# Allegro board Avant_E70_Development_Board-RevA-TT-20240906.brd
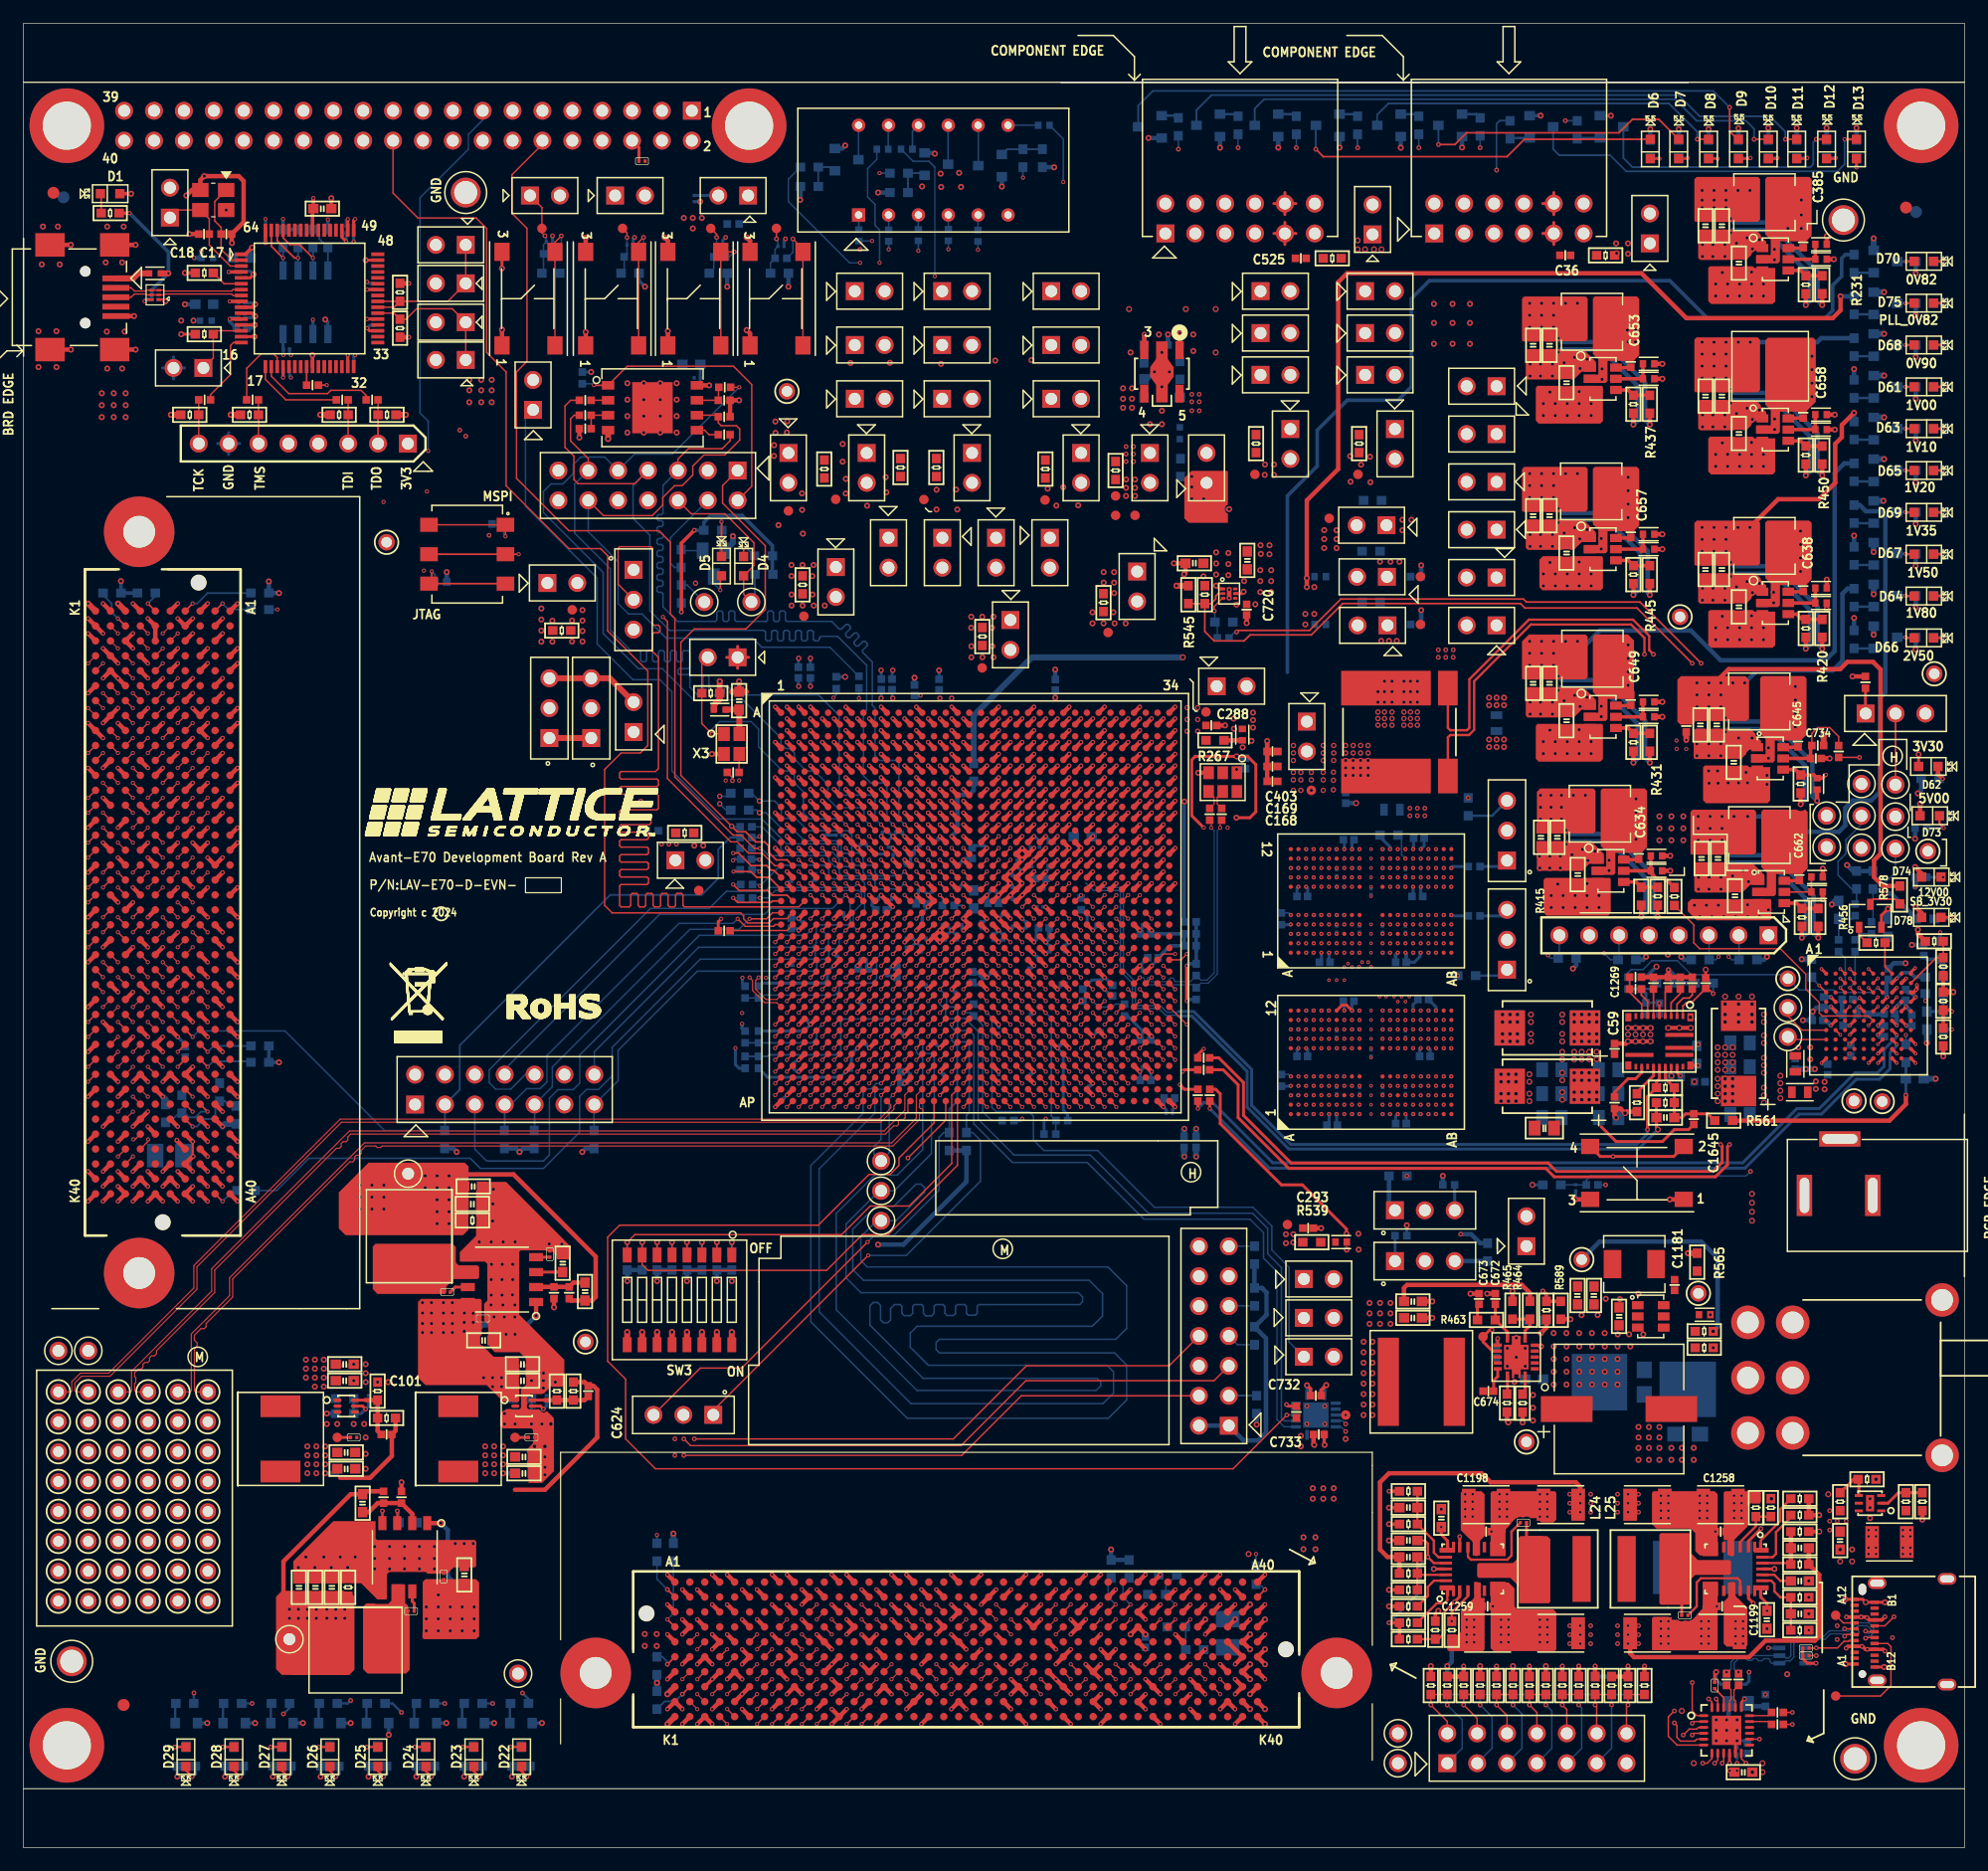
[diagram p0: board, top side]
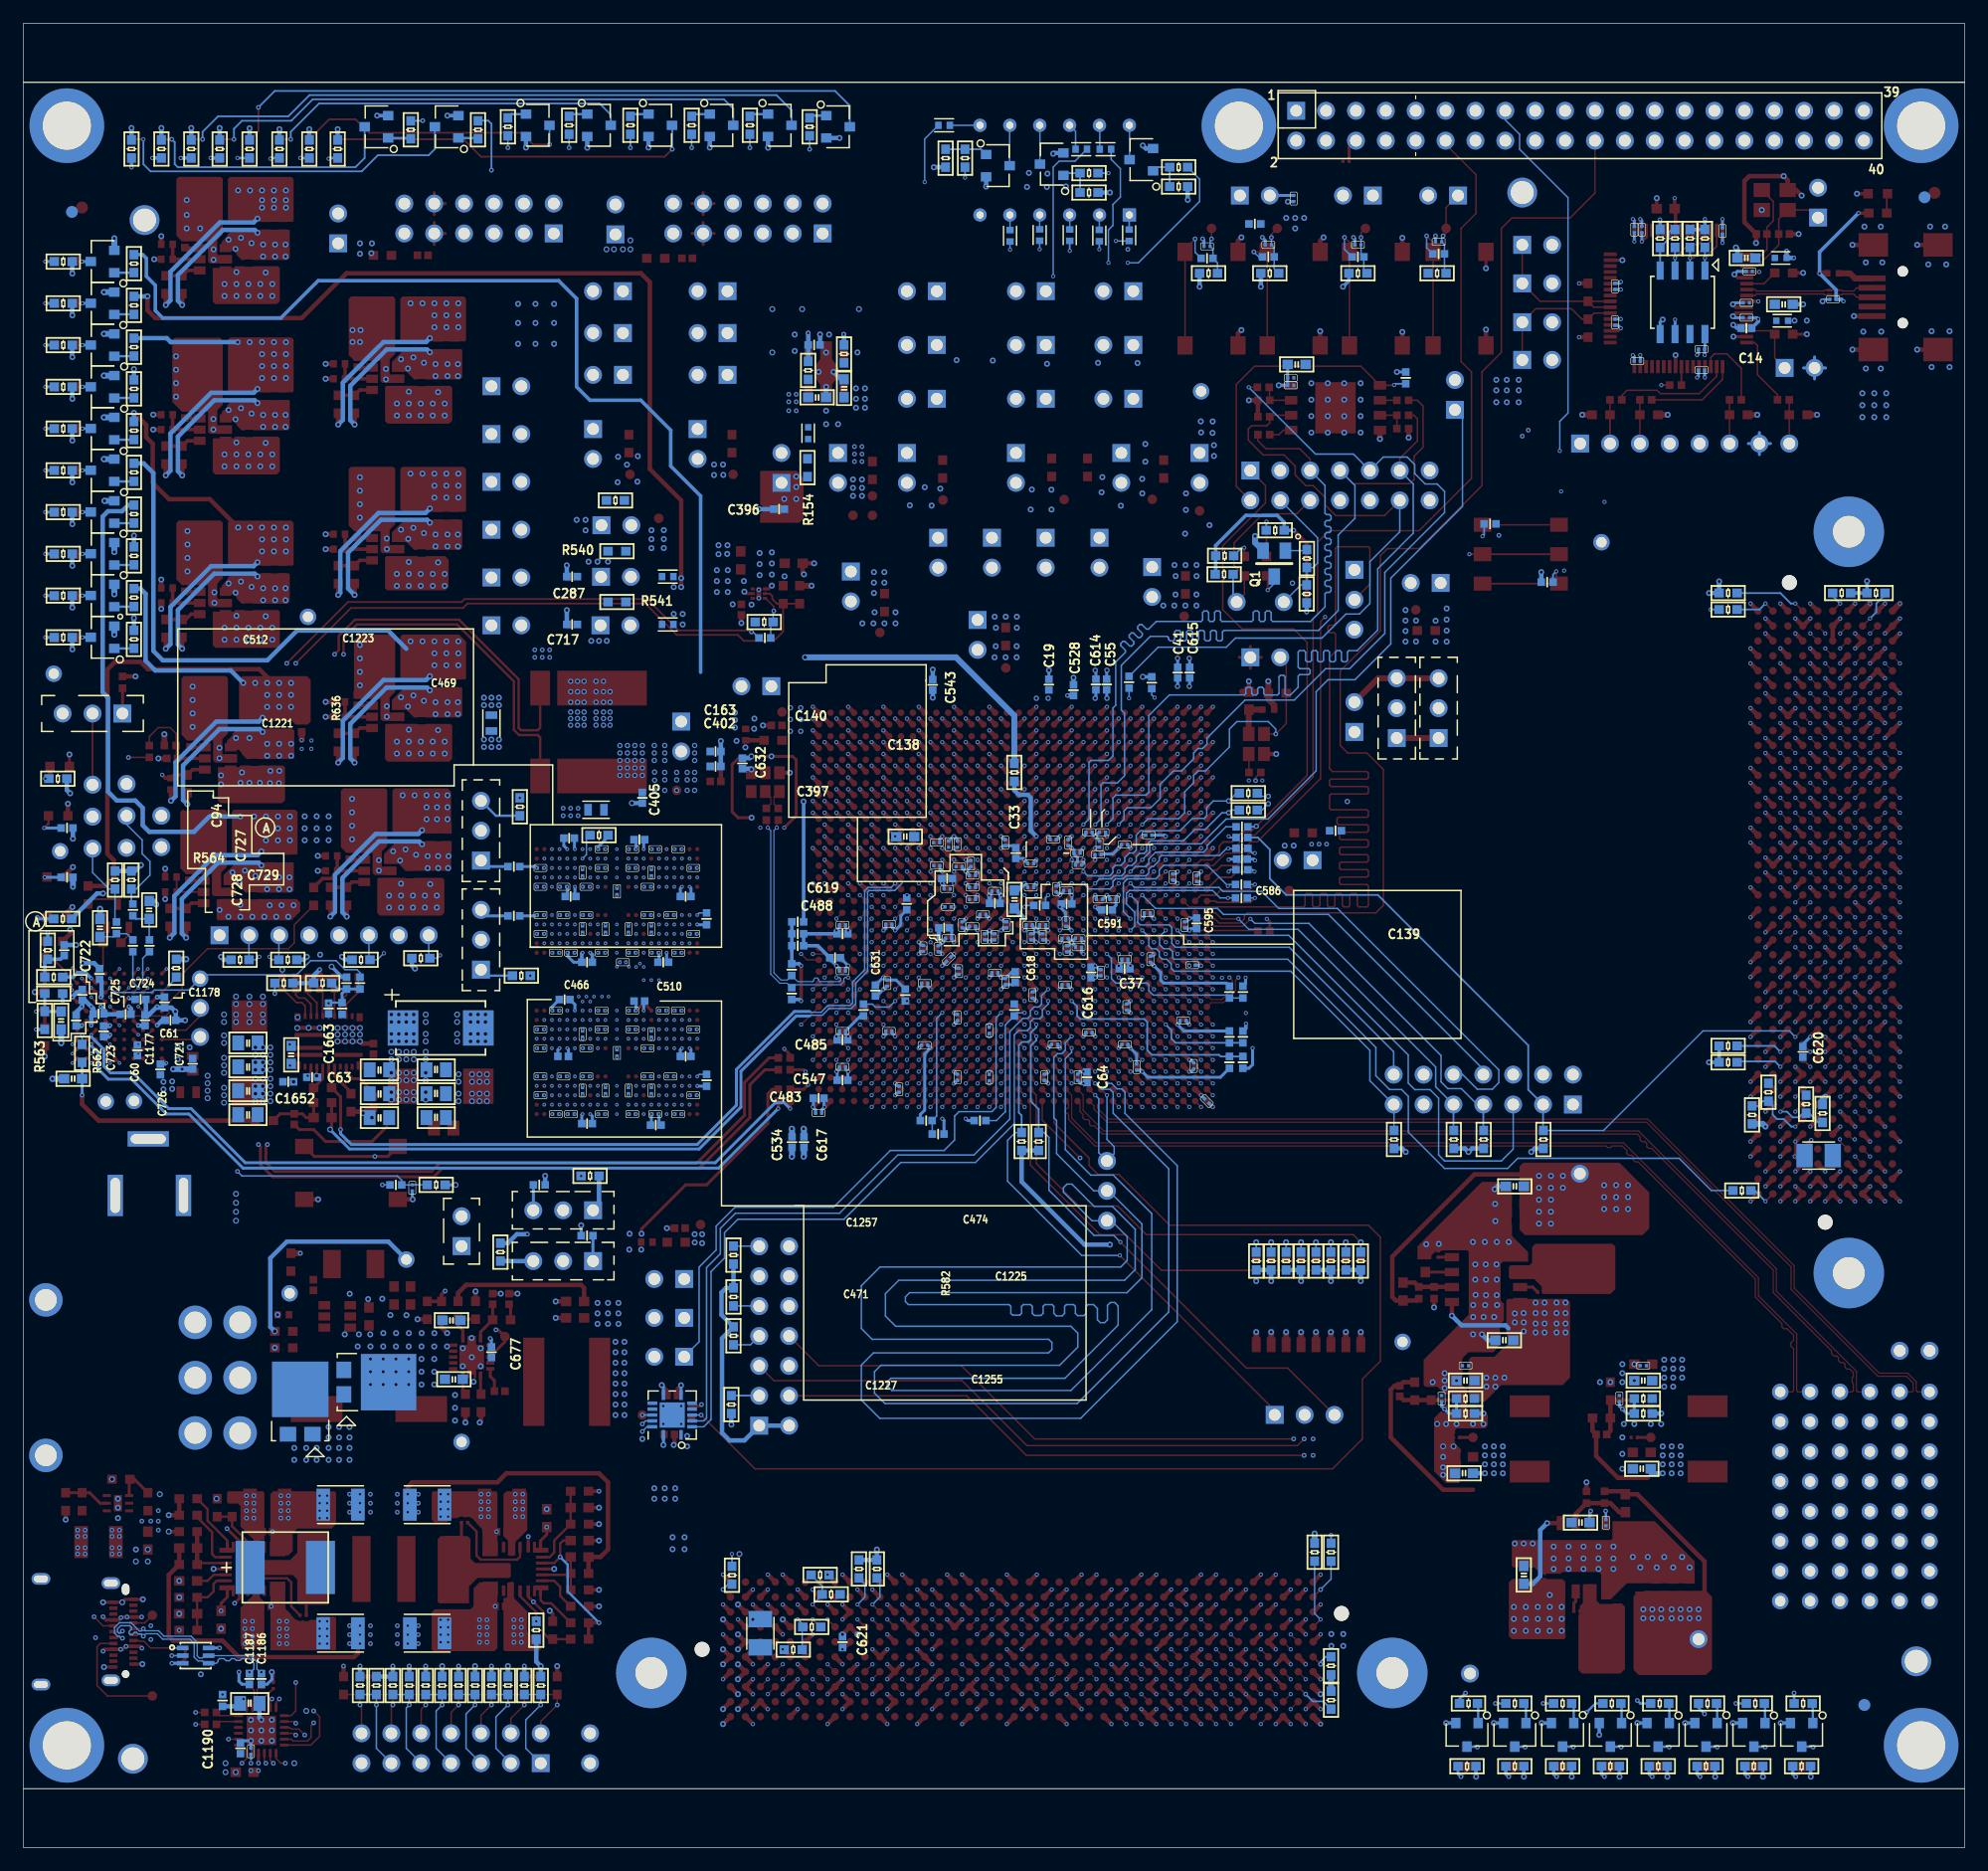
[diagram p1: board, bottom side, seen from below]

Outline 165 x 155 mm; copper layers: TOP, L02-GND, L03-SIG1, L04-GND, L05-SIG2, L06-GND, L07_POW1, L08-POW2, L09-GND, L10-SIG3, L11-GND, L12-SIG4, L13-GND, BOTTOM. Coordinates in mm from the lower left corner of the outline.
Outline path: 0,150 0,155 165,155 165,150 ; 0,150 0,5 ; 0,150 165,150 ; 0,150 165,150 ; 0,150 165,150 ; 0,5 0,0 165,0 165,5 ; 0,5 165,5 ; 0,5 165,5 ; 165,150 165,5

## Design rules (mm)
net group DIFFPAIR4: nets DM DP
net group DP1: nets EPS1_AN13_P EPS1_AP13_N
net group DP2: nets EPS2_AJ16 EPS2_AK16
net group DP3: nets EPS3_AL13_P EPS3_AM13_N
net group DP4: nets EPS4_AG15_P EPS4_AH15_N
net group DP5: nets EPS5_AK12_N EPS5_AK13_P
net group DP6: nets EPS6_AF15_P EPS6_AF16_N
net group DP7: nets EPS7_AN12_N EPS7_AP12_P
net group DP8: nets EPS8_AG14_N EPS8_AH14_P
net group DP9: nets EPS9_AP10_P EPS9_AP11_N
net group DP10: nets EPS10_AK14_P EPS10_AK15_N
net group DP13: nets N21269868 N21466678
net group F_DDR_100MHZ: nets F_DDR_100MHZ_N F_DDR_100MHZ_P
net group LPDDR4_LDM_A: nets LPDDR4_LDQS_A_N LPDDR4_LDQS_A_P
net group LPDDR4_LDM_C: nets LPDDR4_LDQS_C_N LPDDR4_LDQS_C_P
net group LPDDR4_UDM_A: nets LPDDR4_UDQS_A_N LPDDR4_UDQS_A_P
net group LPDDR4_UDM_C: nets LPDDR4_UDQS_C_N LPDDR4_UDQS_C_P
net group LPDDR4_UDM_D: nets LPDDR4_UDQS_D_N LPDDR4_UDQS_D_P
net group PWR: nets VBUS_5V00 VCCBAT_1V50
net group USB_DM: nets N22506509 USB_DM
net group USB_DP: nets N22506512 USB_DP
net group J48_FMC: nets FMC1_CLK0_M2C_N FMC1_CLK0_M2C_P FMC1_CLK1_M2C_N FMC1_CLK1_M2C_P FMC1_CLK3_M2C_N FMC1_CLK3_M2C_P FMC1_HA00_CLK_N FMC1_HA00_CLK_P FMC1_HA01_CLK_N FMC1_HA01_CLK_P FMC1_HA02_N FMC1_HA02_P FMC1_HA04_N FMC1_HA04_P FMC1_HA05_N FMC1_HA05_P FMC1_HA06_N FMC1_HA06_P FMC1_HA10_N FMC1_HA10_P FMC1_HA11_N FMC1_HA11_P FMC1_HA13_N FMC1_HA13_P FMC1_HA14_N FMC1_HA14_P FMC1_HA15_N FMC1_HA15_P FMC1_HA16_N FMC1_HA16_P FMC1_HA18_N FMC1_HA18_P FMC1_HA19_N FMC1_HA19_P FMC1_HA20_N FMC1_HA20_P FMC1_HA21_N FMC1_HA21_P FMC1_HA22_N FMC1_HA22_P FMC1_HA23_N FMC1_HA23_P FMC1_LA00_CLK_N FMC1_LA00_CLK_P FMC1_LA02_N FMC1_LA02_P FMC1_LA03_N FMC1_LA03_P FMC1_LA04_N FMC1_LA04_P FMC1_LA08_N FMC1_LA08_P FMC1_LA09_N FMC1_LA09_P FMC1_LA11_N FMC1_LA11_P FMC1_LA12_N FMC1_LA12_P FMC1_LA13_N FMC1_LA13_P FMC1_LA14_N FMC1_LA14_P FMC1_LA15_N FMC1_LA15_P FMC1_LA16_N FMC1_LA16_P FMC1_LA17_CLK_N FMC1_LA17_CLK_P FMC1_LA18_CLK_N FMC1_LA18_CLK_P FMC1_LA21_N FMC1_LA21_P FMC1_LA22_N FMC1_LA22_P FMC1_LA23_N FMC1_LA23_P FMC1_LA24_N FMC1_LA24_P FMC1_LA25_N FMC1_LA25_P FMC1_LA26_N FMC1_LA26_P FMC1_LA27_N FMC1_LA27_P FMC1_LA28_N FMC1_LA28_P FMC1_LA30_N FMC1_LA30_P FMC1_LA31_N FMC1_LA31_P FMC1_LA32_N FMC1_LA32_P FMC1_LA33_N FMC1_LA33_P
net group J54_FMC: nets FMC2_CLK0_M2C_N FMC2_CLK0_M2C_P FMC2_HA00_CLK_N FMC2_HA00_CLK_P FMC2_HA01_CLK_N FMC2_HA01_CLK_P FMC2_HA02_N FMC2_HA02_P FMC2_HA05_N FMC2_HA05_P FMC2_HA06_N FMC2_HA06_P FMC2_HA07_N FMC2_HA07_P FMC2_HA08_N FMC2_HA08_P FMC2_HA09_N FMC2_HA09_P FMC2_HA10_N FMC2_HA10_P FMC2_HA11_N FMC2_HA11_P FMC2_LA01_CLK_N FMC2_LA01_CLK_P FMC2_LA02_N FMC2_LA02_P FMC2_LA03_N FMC2_LA03_P FMC2_LA04_N FMC2_LA04_P FMC2_LA05_N FMC2_LA05_P FMC2_LA06_N FMC2_LA06_P FMC2_LA07_N FMC2_LA07_P FMC2_LA08_N FMC2_LA08_P FMC2_LA10_N FMC2_LA10_P FMC2_LA11_N FMC2_LA11_P FMC2_LA12_N FMC2_LA12_P FMC2_LA14_N FMC2_LA14_P FMC2_LA15_N FMC2_LA15_P FMC2_LA16_N FMC2_LA16_P FMC2_LA17_CLK_N FMC2_LA17_CLK_P FMC2_LA18_CLK_N FMC2_LA18_CLK_P FMC2_LA19_N FMC2_LA19_P FMC2_LA20_N FMC2_LA20_P FMC2_LA21_N FMC2_LA21_P FMC2_LA22_N FMC2_LA22_P FMC2_LA24_N FMC2_LA24_P FMC2_LA27_N FMC2_LA27_P FMC2_LA29_N FMC2_LA29_P FMC2_LA30_N FMC2_LA30_P FMC2_LA31_N FMC2_LA31_P FMC2_LA32_N FMC2_LA32_P FMC2_LA33_N FMC2_LA33_P
net group LED: nets LED_0 LED_1 LED_2 LED_3 LED_4 LED_5 LED_6 LED_7 LED_8 LED_9 LED_10 LED_11 LED_12 LED_13 LED_14 LED_15
net group LPDDR4_UDM_B: nets LPDDR4_DQ8_B LPDDR4_DQ9_B LPDDR4_DQ10_B LPDDR4_DQ11_B LPDDR4_DQ12_B LPDDR4_DQ13_B LPDDR4_DQ14_B LPDDR4_DQ15_B LPDDR4_UDM_B LPDDR4_UDQS_B_N LPDDR4_UDQS_B_P
net group POWER: nets FMC1_VREFA FMC2_VREFA N23029118
net group USB_VBUS: nets N22506572

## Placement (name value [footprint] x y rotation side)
AP14  TestPoint_SMT  [TPC32]  112.4 36.75 0 top
ASC_CLK  VTTVREF  [TP_50]  149.99 71.34 0 top
C1  0.1uF  [C0201]  27.81 126.31 0 bottom
C2  0.1uF  [C0201]  29.72 132.66 90 bottom
C3  0.1uF  [C0201]  22.35 125.55 0 bottom
C4  0.1uF  [C0201]  27.43 137.49 270 bottom
C5  4.7uF  [C0603]  25.4 139.27 0 top
C6  4.7uF  [C0603]  15.37 131.14 180 bottom
C7  0.1uF  [C0201]  18.54 131.27 0 bottom
C8  0.1uF  [C0201]  11.18 131.56 0 bottom
C9  4.7uF  [C0603]  18.54 135.08 0 bottom
C10  0.1uF  [C0201]  18.29 133.93 0 bottom
C11  0.1uF  [C0201]  29.72 129.62 270 bottom
C12  0.1uF  [C0201]  28.07 137.49 270 bottom
C13  0.1uF  [C0201]  20.57 137.36 90 bottom
C14  10uF  [C0402]  18.54 129.11 0 bottom
C15  0.1uF  [C0201]  18.54 130 0 bottom
C16  0.1uF  [C0201]  22.35 127.33 0 bottom
C17  18pF  [C0402]  17.24 137.11 180 top
C18  18pF  [C0402]  15.34 137.11 0 top
C19  10uF  [C0402]  77.83 98.82 90 bottom
C20  0.1uF  [C0201]  73.53 85.26 90 bottom
C21  0.1uF  [C0201]  51.56 136.19 0 bottom
C22  0.1uF  [C0201]  44.7 136.44 0 bottom
C23  0.1uF  [C0201]  57.28 124.25 0 bottom
C24  0.1uF  [C0201]  57.28 124.89 180 bottom
C25  1uF  [C0603]  56.77 126.03 180 bottom
C26  0.1uF  [C0201]  59.18 136.19 0 bottom
C27  0.1uF  [C0201]  64.39 136.06 0 bottom
C29  50pF  [C0603]  158.5 78.15 270 bottom
C30  50pF  [C0603]  154.31 79.68 270 bottom
C31  0.1uF  [C0201]  77.47 85.64 0 bottom
C32  0.1uF  [C0201]  81.53 85.39 90 bottom
C33  10uF  [C0402]  80.65 84.5 270 bottom
C34  0.1uF  [C0201]  131.95 56.05 270 bottom
C36  10uF  [C0402]  131.06 135.3 180 top
C37  10uF  [C0402]  71.4 74.67 180 bottom
C38  0.1uF  [C0201]  73.41 74.34 90 bottom
C39  0.1uF  [C0201]  71.37 75.48 180 bottom
C40  0.1uF  [C0201]  65.66 74.98 180 bottom
C41  10uF  [C0402]  66.89 99.84 90 bottom
C42  0.1uF  [C0201]  66.42 70.28 180 bottom
C43  0.1uF  [C0201]  64.41 63.43 225 bottom
C44  0.1uF  [C0201]  71.25 71.42 270 bottom
C45  10uF  [C0603]  39.12 43.1 0 top
C46  0.1uF  [C0201]  39.05 44.96 0 top
C47  10uF  [C0603]  39.12 43.1 0 bottom
C48  0.1uF  [C0201]  36.01 47.2 180 top
C49  22uF  [C0603]  38.23 56.18 0 bottom
C50  22uF  [C0603]  38.23 56.18 0 top
C51  22uF  [C0603]  38.16 54.68 0 top
C52  0.1nF  [C0603]  47.73 47.24 90 top
C53  1uF  [C0603]  45.83 49.66 90 top
C54  3.3nF  [C0201]  44.74 50.43 90 top
C55  10uF  [C0402]  72.92 98.84 90 bottom
C56  0.1uF  [C0201]  76.45 73.33 180 bottom
C57  0.1uF  [C0201]  70.38 66.32 90 bottom
C58  0.1uF  [C0201]  74.42 69.26 180 bottom
C59  1uF  [C0402]  135.25 67.86 90 top
C60  0.1uF  [C0402]  155.32 67.74 270 bottom
C61  0.1uF  [C0402]  152.51 70.3 180 bottom
C62  33nF  [C0603]  139.57 62.02 180 top
C63  1uF  [C0402]  140.46 65.45 180 bottom
C64  10uF  [C0402]  74.6 65.45 270 bottom
C65  0.1uF  [C0201]  79.25 72.44 270 bottom
C66  0.1uF  [C0201]  75.39 65.45 270 bottom
C69  1uF  [C0603]  60.83 97.46 90 top
C94  10nF  [C0402]  161.54 76.25 90 bottom
C97  10uF  [C0603]  27.3 39.67 0 top
C98  10uF  [C0603]  27.3 39.67 0 bottom
C99  0.1uF  [C0201]  27.3 40.94 0 bottom
C100  0.1uF  [C0201]  28.07 34.84 0 top
C101  18pF-DNI  [C0402]  30.86 35.1 180 top
C103  22uF  [C0603]  27.43 33.57 0 top
C104  22uF  [C0603]  27.43 32.18 0 bottom
C113  560 uF/25V  [RAD_CAN_A768MS]  135.64 37.26 180 top
C138  10uF  [C0402]  82.43 80.23 0 bottom
C139  10uF  [C0402]  76.33 80.18 180 bottom
C140  10uF  [C0402]  86.49 82.34 180 bottom
C142  0.1uF  [C0201]  87.36 83.44 180 bottom
C143  0.1uF  [C0201]  76.33 81.33 0 bottom
C144  0.1uF  [C0201]  85.6 85.26 90 bottom
C145  0.1uF  [C0201]  84.33 80.56 180 bottom
C146  0.1uF  [C0201]  87.38 85.39 180 bottom
C147  0.1uF  [C0201]  76.45 77.26 180 bottom
C148  0.1uF  [C0201]  82.42 81.29 180 bottom
C149  0.1uF  [C0201]  86.49 81.45 0 bottom
C150  0.1uF  [C0201]  85.47 83.36 180 bottom
C151  0.1uF  [C0201]  84.33 81.58 0 bottom
C152  0.1uF  [C0201]  79.5 78.41 180 bottom
C163  10uF  [C0402]  106.17 93.14 0 bottom
C164  0.1uF  [C0201]  82.42 77.39 90 bottom
C165  0.1uF  [C0201]  84.33 78.28 0 bottom
C166  0.1uF  [C0201]  75.31 76.5 0 bottom
C167  0.1uF  [C0201]  86.36 75.48 315 bottom
C168  10uF  [C0402]  106.17 90.6 0 top
C169  10uF  [C0402]  106.17 91.87 0 top
C171  0.1uF  [C0201]  84.46 83.61 270 bottom
C172  0.1uF  [C0201]  83.44 79.29 0 bottom
C173  0.1uF  [C0201]  76.4 78.53 90 bottom
C174  0.1uF  [C0201]  86.36 85.26 90 bottom
C175  0.1uF  [C0201]  85.22 78.41 270 bottom
C176  0.1uF  [C0201]  78.36 78.41 0 bottom
C177  0.1uF  [C0201]  83.31 77.39 90 bottom
C178  0.1uF  [C0201]  84.33 82.6 0 bottom
C207  10uF  [C0603]  95.25 124 90 bottom
C208  10uF  [C0603]  97.54 123.24 180 bottom
C287  10nF  [C0402]  118.36 108 0 bottom
C288  10nF  [C0402]  100.97 95.35 0 top
C289  0.1uF  [C0201]  76.33 76.37 90 bottom
C290  0.1uF  [C0201]  87.25 76.37 90 bottom
C291  0.1uF  [C0201]  75.31 83.49 0 bottom
C292  0.1uF  [C0201]  79.38 77.39 90 bottom
C293  10nF  [C0402]  109.2 52.63 0 top
C385  0.1uF  [C0402]  151.28 136.4 90 top
C386  22uF  [C0603]  144.39 137.81 270 top
C387  22uF  [C0603]  142.99 137.81 270 top
C388  10uF  [C0603]  145.82 134.64 90 top
C396  10uF  [C0402]  100.77 113.73 0 bottom
C397  10uF  [C0402]  86.74 78.15 0 bottom
C398  0.1uF  [C0201]  86.36 77.26 0 bottom
C399  0.1uF  [C0201]  81.41 78.41 90 bottom
C400  0.1uF  [C0201]  73.66 84.37 180 bottom
C401  0.1uF  [C0201]  75.31 77.26 0 bottom
C402  10uF  [C0402]  106.17 91.87 0 bottom
C403  10uF  [C0402]  106.17 93.14 0 top
C404  0.1uF  [C0201]  78.36 77.39 90 bottom
C405  10uF  [C0402]  112.4 89.2 90 bottom
C465  0.1uF  [C0201]  91.44 78.46 0 bottom
C466  10uF  [C0402]  117.09 75.23 0 bottom
C467  0.1uF  [C0201]  110 79.24 0 bottom
C468  0.1uF  [C0201]  88.5 76.41 90 bottom
C469  10uF  [C0402]  108.71 80.82 0 bottom
C470  0.1uF  [C0201]  108.05 83.24 180 bottom
C471  10uF  [C0402]  119.13 67.23 180 bottom
C472  0.1uF  [C0201]  113.25 84.84 180 bottom
C473  0.1uF  [C0201]  88.39 73.45 0 bottom
C474  10uF  [C0402]  112.65 71.93 0 bottom
C475  0.1uF  [C0201]  113.25 62.32 180 bottom
C476  0.1uF  [C0201]  85.47 74.47 270 bottom
C477  0.1uF  [C0201]  119.75 62.32 0 bottom
C478  0.1uF  [C0201]  91.57 73.45 270 bottom
C479  0.1uF  [C0201]  121.05 65.52 0 bottom
C480  0.1uF  [C0201]  95.38 74.47 0 bottom
C481  0.1uF  [C0201]  121.05 63.92 0 bottom
C482  0.1uF  [C0201]  119.1 65.52 180 bottom
C483  10uF  [C0402]  97.41 63.67 0 bottom
C484  0.1uF  [C0201]  109.35 71.12 180 bottom
C485  10uF  [C0402]  95.38 68.63 0 bottom
C486  0.1uF  [C0201]  121.05 67.92 0 bottom
C487  0.1uF  [C0201]  117.48 78.04 270 bottom
C488  10uF  [C0402]  96.01 75.61 0 bottom
C489  0.1uF  [C0201]  111.63 82.84 90 bottom
C490  0.1uF  [C0201]  121.05 69.52 0 bottom
C491  0.1uF  [C0201]  117.48 82.84 90 bottom
C492  0.1uF  [C0201]  115.85 69.52 0 bottom
C493  0.1uF  [C0201]  111.3 84.84 0 bottom
C494  0.1uF  [C0201]  111.63 78.04 270 bottom
C495  0.1uF  [C0201]  117.15 65.52 0 bottom
C496  0.1uF  [C0201]  111.3 76.04 0 bottom
C497  0.1uF  [C0201]  118.45 76.04 0 bottom
C498  0.1uF  [C0201]  111.95 67.92 180 bottom
C499  0.1uF  [C0201]  113.25 71.12 180 bottom
C500  0.1uF  [C0201]  109.35 84.84 180 bottom
C501  0.1uF  [C0201]  111.95 79.24 180 bottom
C502  0.1uF  [C0201]  108.06 77.64 180 bottom
C503  0.1uF  [C0201]  113.25 76.04 180 bottom
C504  0.1uF  [C0201]  109.35 76.04 180 bottom
C505  0.1uF  [C0201]  113.58 78.04 90 bottom
C506  0.1uF  [C0201]  111.95 81.64 180 bottom
C507  0.1uF  [C0201]  86.41 79.93 0 bottom
C508  0.1uF  [C0201]  113.25 83.24 180 bottom
C509  0.1uF  [C0201]  95.38 78.41 0 bottom
C510  10uF  [C0402]  110.62 75.23 180 bottom
C511  0.1uF  [C0201]  115.53 64.32 90 bottom
C512  10uF  [C0402]  118.62 85.77 0 bottom
C525  10uF  [C0402]  108.59 135.05 180 top
C526  0.1uF  [C0201]  79.38 83.61 0 bottom
C527  0.1uF  [C0201]  77.22 81.45 270 bottom
C528  10uF  [C0402]  75.74 98.34 90 bottom
C529  0.1uF  [C0201]  76.2 85.39 270 bottom
C530  0.1uF  [C0201]  79.38 81.58 0 bottom
C531  0.1uF  [C0201]  69.22 75.48 90 bottom
C532  0.1uF  [C0201]  65.51 66.41 270 bottom
C533  0.1uF  [C0201]  71.37 68.25 180 bottom
C534  10uF  [C0402]  99.67 59.94 270 bottom
C535  0.1uF  [C0201]  82.42 74.34 180 bottom
C536  0.1uF  [C0201]  85.6 70.53 270 bottom
C537  0.1uF  [C0201]  81.53 73.58 90 bottom
C538  0.1uF  [C0201]  82.91 65.43 270 bottom
C539  0.1uF  [C0201]  85.6 65.45 270 bottom
C540  0.1uF  [C0201]  90.55 64.44 270 bottom
C541  0.1uF  [C0201]  88.4 68.19 0 bottom
C542  0.1uF  [C0201]  97.41 62.4 0 bottom
C543  10uF  [C0402]  87.71 98.8 90 bottom
C544  0.1uF  [C0201]  82.91 69.44 270 bottom
C545  0.1uF  [C0201]  95.38 66.34 0 bottom
C546  0.1uF  [C0201]  95.38 69.39 0 bottom
C547  10uF  [C0402]  95.38 65.2 0 bottom
C548  0.1uF  [C0201]  91.44 69.39 0 bottom
C556  22uF  [C0603]  23.41 22.1 90 top
C557  22uF  [C0603]  24.8 22.1 90 top
C558  10uF  [C0603]  37.46 23.16 90 top
C559  0.1nF  [C0603]  28.83 29.26 270 top
C560  10uF  [C0603]  37.46 23.16 90 bottom
C561  0.1uF  [C0201]  35.71 23.03 90 top
C562  1uF  [C0603]  32.64 27.61 0 bottom
C563  3.3nF  [C0201]  30.48 27.61 270 bottom
C564  0.1uF  [C0201]  32.95 20.09 180 top
C565  22uF  [C0603]  26.2 22.1 90 top
C579  0.1uF  [C0201]  77.34 68.25 180 bottom
C580  0.1uF  [C0201]  78.23 65.45 270 bottom
C584  0.1uF  [C0201]  67.31 82.47 270 bottom
C586  10uF  [C0402]  61.42 83.99 180 bottom
C587  0.1uF  [C0201]  73.28 86.28 0 bottom
C588  0.1uF  [C0201]  65.28 82.34 270 bottom
C589  0.1uF  [C0201]  71.4 85.23 0 bottom
C590  0.1uF  [C0201]  69.34 86.03 180 bottom
C591  10uF  [C0402]  72.9 79.68 0 bottom
C592  0.1uF  [C0201]  75.44 84.5 0 bottom
C593  0.1uF  [C0201]  73.53 80.56 180 bottom
C594  0.1uF  [C0201]  72.39 80.56 0 bottom
C595  10uF  [C0402]  65.28 78.53 270 bottom
C596  0.1uF  [C0201]  69.47 79.42 180 bottom
C597  0.1uF  [C0201]  66.29 78.41 270 bottom
C598  0.1uF  [C0201]  74.42 86.28 180 bottom
C599  0.1uF  [C0201]  52.58 143.3 180 top
C600  0.1uF  [C0201]  57.02 140.13 270 bottom
C612  22uF  [C0603]  80.77 80.56 90 bottom
C613  22uF  [C0603]  90.04 85.9 0 bottom
C614  10uF  [C0402]  73.83 98.84 90 bottom
C615  10uF  [C0402]  65.87 99.84 90 bottom
C616  10uF  [C0402]  74.24 74.37 90 bottom
C617  10uF  [C0402]  98.66 59.94 270 bottom
C618  10uF  [C0402]  80.7 73.96 90 bottom
C619  10uF  [C0402]  95.38 77.64 0 bottom
C620  10uF  [C0402]  13.74 67.61 270 bottom
C621  10uF  [C0402]  95.38 17.45 90 bottom
C622  22uF  [C0603]  42.55 31.8 0 top
C623  10uF  [C0603]  42.42 39.67 0 top
C624  18pF-DNI  [C0402]  48.01 38.78 270 top
C625  0.1uF  [C0201]  42.42 40.94 0 bottom
C626  10uF  [C0603]  42.42 41.07 0 top
C628  22uF  [C0603]  42.55 31.8 0 bottom
C629  0.1uF  [C0201]  43.18 34.84 0 top
C630  22uF  [C0603]  42.55 33.19 0 top
C631  10uF  [C0402]  92.58 72.82 270 bottom
C632  0.1uF  [C0402]  103.89 92.12 90 bottom
C634  0.1uF  [C0402]  137.3 84.43 90 top
C635  22uF  [C0603]  130.4 85.84 270 top
C636  22uF  [C0603]  129.01 85.84 270 top
C637  10uF  [C0603]  132.12 82.68 90 top
C638  0.1uF  [C0402]  151.28 107.19 90 top
C639  22uF  [C0603]  144.39 108.6 270 top
C640  22uF  [C0603]  142.99 108.6 270 top
C641  10uF  [C0603]  145.82 105.43 90 top
C642  22uF  [C0603]  142.56 95.39 270 top
C643  22uF  [C0603]  143.95 95.39 270 top
C644  10uF  [C0603]  145.38 92.22 90 top
C645  0.1uF  [C0402]  150.85 93.98 90 top
C646  22uF  [C0603]  129.74 98.93 270 top
C647  22uF  [C0603]  128.34 98.93 270 top
C648  10uF  [C0603]  131.16 95.75 90 top
C649  0.1uF  [C0402]  136.63 97.52 90 top
C650  22uF  [C0603]  129.74 127.65 270 top
C651  22uF  [C0603]  128.34 127.65 270 top
C652  10uF  [C0603]  131.16 124.48 90 top
C653  0.1uF  [C0402]  136.63 126.24 90 top
C654  22uF  [C0603]  129.74 113.18 270 top
C655  22uF  [C0603]  128.34 113.18 270 top
C656  10uF  [C0603]  131.16 110 90 top
C657  0.1uF  [C0402]  136.63 111.77 90 top
C658  0.1uF  [C0402]  151.28 121.93 90 top
C659  22uF  [C0603]  142.99 123.34 270 top
C660  22uF  [C0603]  144.39 123.34 270 top
C661  10uF  [C0603]  145.82 120.16 90 top
C662  0.1uF  [C0402]  150.95 82.63 90 top
C663  22uF  [C0603]  142.66 84.04 270 top
C664  22uF  [C0603]  144.06 84.04 270 top
C665  10uF  [C0603]  145.48 80.87 90 top
C672  180pF  [C0402]  125.12 46.61 90 top
C673  8.2nF  [C0402]  123.72 46.61 90 top
C674  0.1uF  [C0402]  124.53 38.78 180 top
C675  22uF  [C0603]  118.11 45 0 top
C676  22uF  [C0603]  118.11 46.4 0 top
C677  10nF  [C0402]  125.22 42.08 90 bottom
C713  22uF  [C0603]  128.42 39.79 180 bottom
C714  22uF  [C0603]  128.62 44.8 180 bottom
C717  10nF  [C0402]  118.36 103.93 0 bottom
C718  10uF  [C0603]  104.03 109.38 90 top
C719  10uF  [C0603]  99.53 109.13 180 top
C720  0.1uF  [C0402]  103.98 105.19 270 top
C721  10uF  [C0402]  150.62 66.59 270 bottom
C722  0.1uF  [C0402]  158.54 74.23 90 bottom
C723  0.1uF  [C0402]  158.18 69.36 90 bottom
C724  0.1uF  [C0402]  155.05 72.07 180 bottom
C725  0.1uF  [C0402]  156.32 70.8 0 bottom
C726  10uF  [C0402]  153.37 66.12 90 bottom
C727  0.1uF  [C0402]  160 72.45 90 bottom
C728  0.1uF  [C0402]  160.53 70.28 270 bottom
C729  0.1uF  [C0402]  158.62 70.84 180 bottom
C732  0.1uF  [C0402]  109.85 38.4 180 top
C733  0.1uF  [C0402]  110.11 35.1 180 top
C734  0.1uF-DNI  [C0402]  152.37 92.55 0 top
C1177  0.1uF  [C0402]  154.67 70.3 90 bottom
C1178  0.1uF  [C0402]  153.02 71.82 270 bottom
C1179  1nF  [C0603]  160.78 65.32 0 bottom
C1180  1nF  [C0603]  161.8 70.28 270 bottom
C1181  0.1uF  [C0402]  140.36 47.8 90 top
C1182  10uF  [C0603]  135.64 45.13 90 top
C1183  22uF  [C0603]  132.11 46.91 270 top
C1184  22uF  [C0603]  133.5 46.91 270 top
C1185  0.1uF/50V  [C0805]  145.77 12.24 180 bottom
C1186  10nF  [C0402]  144.78 14.32 270 bottom
C1187  10nF  [C0402]  145.8 14.32 270 bottom
C1188  390pF  [C0201]  151.51 16.94 180 top
C1189  390pF  [C0201]  151.51 16.3 180 top
C1190  10uF  [C0402]  146.56 8.43 90 bottom
C1191  0.1uF  [C0201]  145.67 8.17 90 bottom
C1192  0.1uF  [C0201]  143.76 13.76 270 top
C1193  10uF/50V  [C1210]  124.33 29.13 0 top
C1194  10uF/50V  [C1210]  124.46 18.21 0 top
C1195  10uF/50V  [C1210]  144.27 29.13 180 top
C1196  10uF/50V  [C1210]  144.4 18.21 180 top
C1198  0.1uF/50V  [C0402]  124.33 26.84 0 top
C1199  0.1uF/50V  [C0402]  144.4 20.49 180 top
C1202  0.1uF  [C0201]  141.22 19.73 180 top
C1203  0.1uF  [C0201]  127.51 27.61 0 top
C1204  47uF  [C1210]  130.68 29.13 180 bottom
C1205  47uF  [C1210]  130.68 18.21 180 top
C1206  47uF  [C1210]  130.68 29.13 180 top
C1207  47uF  [C1210]  130.68 18.21 180 bottom
C1208  47uF  [C1210]  138.05 18.21 0 top
C1209  47uF  [C1210]  138.05 18.21 0 bottom
C1210  47uF  [C1210]  138.05 29.13 0 bottom
C1211  47uF  [C1210]  138.05 29.13 0 top
C1214  1nF  [C0603]  148.21 19.35 270 top
C1215  1nF  [C0603]  120.52 27.99 90 top
C1216  10uF  [C0603]  27.3 41.07 0 top
C1217  22uF  [C0603]  27.43 32.18 0 top
C1218  10uF  [C0603]  42.42 39.67 0 bottom
C1219  0.1uF  [C0201]  29.34 38.15 270 bottom
C1220  0.1uF  [C0201]  44.45 38.15 270 bottom
C1221  10uF  [C0402]  118.49 80.82 0 bottom
C1222  0.1uF  [C0201]  115.85 83.24 0 bottom
C1223  10uF  [C0402]  112.65 85.64 0 bottom
C1224  0.1uF  [C0201]  115.53 78.04 90 bottom
C1225  10uF  [C0402]  108.71 67.23 0 bottom
C1226  0.1uF  [C0201]  115.85 84.84 0 bottom
C1227  10uF  [C0402]  117.09 61.51 0 bottom
C1228  0.1uF  [C0201]  109.35 62.32 180 bottom
C1229  0.1uF  [C0201]  108.05 69.52 180 bottom
C1230  0.1uF  [C0201]  110 65.52 0 bottom
C1231  0.1uF  [C0201]  111.95 65.52 180 bottom
C1232  0.1uF  [C0201]  115.85 71.12 0 bottom
C1233  0.1uF  [C0201]  119.75 71.12 0 bottom
C1234  0.1uF  [C0201]  117.48 69.12 90 bottom
C1235  0.1uF  [C0201]  117.15 67.92 0 bottom
C1236  0.1uF  [C0201]  111.3 62.32 0 bottom
C1237  0.1uF  [C0201]  118.45 62.32 0 bottom
C1238  0.1uF  [C0201]  108.06 63.92 180 bottom
C1239  0.1uF  [C0201]  110.65 71.12 180 bottom
C1240  0.1uF  [C0201]  113.25 69.52 180 bottom
C1241  0.1uF  [C0201]  111.63 69.12 90 bottom
C1242  0.1uF  [C0201]  113.58 64.32 90 bottom
C1243  0.1uF  [C0201]  111.63 64.32 270 bottom
C1244  0.1uF  [C0201]  117.48 64.32 270 bottom
C1245  0.1uF  [C0201]  115.85 62.32 0 bottom
C1246  0.1uF  [C0201]  121.05 79.24 0 bottom
C1247  0.1uF  [C0201]  119.1 81.64 180 bottom
C1248  0.1uF  [C0201]  117.15 81.64 0 bottom
C1249  0.1uF  [C0201]  121.05 81.64 0 bottom
C1250  0.1uF  [C0201]  121.05 83.24 0 bottom
C1251  0.1uF  [C0201]  117.15 79.24 0 bottom
C1252  0.1uF  [C0201]  119.1 79.24 180 bottom
C1253  0.1uF  [C0201]  115.85 76.04 0 bottom
C1254  0.1uF  [C0201]  121.05 77.64 0 bottom
C1255  10uF  [C0402]  111.25 61.39 0 bottom
C1256  0.1uF  [C0201]  119.75 76.04 0 bottom
C1257  10uF  [C0402]  119 72.06 0 bottom
C1258  0.1uF/50V  [C0402]  144.27 26.84 180 top
C1259  0.1uF/50V  [C0402]  124.46 20.49 0 top
C1260  10uF/50V  [C1210]  158.62 25.95 180 top
C1261  10uF  [C0603]  154.43 26.08 270 top
C1264  1uF  [C0603]  117.73 28.88 180 top
C1265  1uF  [C0603]  151 19.86 0 top
C1266  1uF  [C0603]  117.73 26.08 180 top
C1267  1uF  [C0603]  151 22.65 0 top
C1268  1uF  [C0603]  146.2 6.4 0 top
C1269  1uF  [C0402]  143 73.45 90 top
C1645  10nF_DNI  [C0402]  141.99 61.9 90 top
C1646  0.1u-DNI  [C0603]  142.24 67.36 270 bottom
C1647  100uF  [TC7343]  145.8 67.48 90 top
C1648  22uF  [C0805]  145.92 62.28 0 bottom
C1649  22uF  [C0805]  145.92 66.34 0 bottom
C1650  22uF  [C0805]  145.92 68.37 0 bottom
C1651  22uF  [C0805]  145.92 64.31 0 bottom
C1652  1uF  [C0402]  142.49 65.07 180 bottom
C1653  220uF  [TC7343]  129.54 69.64 180 top
C1654  220uF  [TC7343]  129.54 64.69 180 top
C1655  220uF_DNI  [TC7343]  129.54 69.64 180 bottom
C1656  47uF  [C0805]  129.92 64.05 180 bottom
C1657  47uF  [C0805]  134.75 66.09 0 bottom
C1658  47uF  [C0805]  129.92 62.02 180 bottom
C1659  47uF  [C0805]  134.75 64.05 0 bottom
C1660  47uF  [C0805]  134.75 62.02 0 bottom
C1661  47uF  [C0805]  129.92 66.09 180 bottom
C1662  47uF  [C0805]  129.29 61.13 180 top
C1663  0.01uF_DNI  [C0402]  139.06 71.29 270 bottom
C1665  2pF  [C0201]  114.05 75.23 0 bottom
C1666  50pF  [C0603]  117.73 24.68 0 top
C1667  50pF  [C0603]  151 25.45 180 top
C1668  100uF/35V  [7360-20]  142.75 23.8 180 bottom
D1  GREEN  [APT1608]  7.37 140.54 90 top
D3  ESDR0502N-UDFN6  [UDFN6_040]  11.18 131.94 90 top
D4  GREEN  [APT1608]  61.21 108.89 0 top
D5  GREEN  [APT1608]  59.33 108.89 0 top
D6  GREEN  [APT1608]  138.29 144.34 180 top
D7  GREEN  [APT1608]  140.71 144.34 180 top
D8  GREEN  [APT1608]  143.25 144.34 180 top
D9  GREEN  [APT1608]  145.79 144.34 180 top
D10  GREEN  [APT1608]  148.33 144.34 180 top
D11  GREEN  [APT1608]  150.74 144.34 180 top
D12  GREEN  [APT1608]  153.28 144.34 180 top
D13  GREEN  [APT1608]  155.82 144.34 180 top
D22  GREEN  [APT1608]  42.34 7.71 180 top
D23  GREEN  [APT1608]  38.28 7.71 180 top
D24  GREEN  [APT1608]  34.2 7.71 180 top
D25  GREEN  [APT1608]  30.12 7.71 180 top
D26  GREEN  [APT1608]  26.04 7.71 180 top
D27  GREEN  [APT1608]  21.96 7.71 180 top
D28  GREEN  [APT1608]  17.88 7.71 180 top
D29  GREEN  [APT1608]  13.8 7.71 180 top
D52  V12P10-M3/86A  [TO-277A]  141.48 37.89 180 bottom
D60  LDT-N2804RI  [DISPLAY_12P-PTH]  77.34 142.54 0 top
D61  1V00  [APT1608]  161.54 124.13 270 top
D62  3V30  [APT1608]  161.92 91.87 270 top
D63  1V10  [APT1608]  161.54 120.57 270 top
D64  1V80  [APT1608]  161.54 106.35 270 top
D65  1V20  [APT1608]  161.54 117.01 270 top
D66  2V50  [APT1608]  161.54 102.79 270 top
D67  1V50  [APT1608]  161.54 109.9 270 top
D68  0V90  [APT1608]  161.54 127.68 270 top
D69  1V35  [APT1608]  161.54 113.46 270 top
D70  0V82  [APT1608]  161.54 134.79 270 top
D73  5V00  [APT1608]  162.05 87.68 270 top
D74  12V00  [APT1608]  162.18 82.47 270 top
D75  PLL_0V82  [APT1608]  161.54 131.24 270 top
D77  V12P10-M3/86A  [TO-277A]  135 39.54 270 bottom
D78  SBY_3V30  [APT1608]  162.18 79.04 270 top
DONE  TestPoint  [TP50]  57.87 105.84 180 top
F1_3V3  T POINT R  [TP]  10.58 26.02 180 top
F1_3V3AUX  T POINT R  [TP]  2.96 26.02 180 top
F1_ADJ  T POINT R  [TP]  5.5 26.02 180 top
F2_3V3  T POINT R  [TP]  15.66 26.02 180 top
F2_3V3AUX  T POINT R  [TP]  2.96 23.48 180 top
F2_ADJ  T POINT R  [TP]  5.5 23.48 180 top
FB1  MPZ1005S121CT000  [FB0402]  15.49 129.74 180 bottom
FB2  MPZ1005S121CT000  [FB0402]  11.18 133.77 180 top
FB3  MPZ1005S121CT000  [FB0402]  15.62 135.08 180 bottom
FB4  FBMH2016HM121NT  [0806]  12.4 58.8 0 bottom
FB6  MPZ1005S121CT000  [FB0402]  59.18 96.69 0 top
FB16  MPZ1005S121CT000  [FB0402]  98.3 120.19 270 bottom
FB22  BLM15AX601SN1D  [0402]  103.61 94.57 90 top
FB24  FBMH2016HM121NT  [0806]  102.36 18.21 90 bottom
FB25  BLM15AX601SN1D  [0402]  112.01 51.45 0 top
FB26  BLM15AX601SN1D  [0402]  110.24 108 180 bottom
FB27  BLM15AX601SN1D  [0402]  110.24 103.93 180 bottom
FB28  BLM18KG221SN1D  [FB0603]  116.33 88.18 0 bottom
FB29  BLM18KG221SN1D  [FB0603]  125.22 95.55 270 bottom
GND1  TestPoint_Hole  [TP]  47.77 42.97 0 top
GND2  TestPoint_Hole  [TP]  140.82 104.58 0 top
GND3  TestPoint_Hole  [TP]  162.43 99.74 0 top
GND4  TestPoint_Hole  [TP]  127.76 34.46 0 top
GND5  TestPoint_Hole  [TP]  64.9 123.74 0 top
GND6  T POINT R  [TP]  2.96 28.56 180 top
GND7  T POINT R  [TP]  5.5 28.56 180 top
GND8  T POINT R  [TP]  10.58 28.56 180 top
GND9  T POINT R  [TP]  8.04 28.56 180 top
GND10  T POINT R  [TP]  13.12 28.56 180 top
GND11  T POINT R  [TP]  15.66 28.56 180 top
GND12  T POINT R  [TP]  2.96 33.64 180 top
GND13  T POINT R  [TP]  2.96 36.18 180 top
GND14  T POINT R  [TP]  10.58 33.64 180 top
GND15  T POINT R  [TP]  10.58 36.18 180 top
INIT  TestPoint  [TP50]  61.87 105.84 180 top
J1  Header 1x8  [HDR_AMP_87220_8_1X8_100]  32.67 119.31 180 top
J2  USB_MINI_B  [USB_MINI_B-1734035-2]  0 131.74 270 top
J3  Header_2x7  [HEADER_2X7]  53.09 115.74 180 top
J6  PMOD 2x6  [PPPC062LJBN-RC]  126.28 150 0 top
J7  PMOD 2x6  [PPPC062LJBN-RC]  103.42 150 0 top
J8  CON3  [HDR1X3]  159.14 96.36 0 top
J10  Header_2x7  [HEADER_2X7]  40.9 64.41 0 top
J11  HEADER 2  [22284024]  127.76 52.37 90 top
J23  Header_2x1  [HEADER_2X1]  138.25 137.59 90 top
J25  12401610E4#2A  [USB_TYPEC_RA_SMT]  157.36 18.33 90 top
J31  GND  [TUR_TH]  155.7 7.54 0 top
J32  GND  [TUR_TH]  154.71 138.3 270 top
J33  GND  [TUR_TH]  37.59 140.64 0 top
J39  PTM_JTAG  [HDR_AMP_87220_8_1X8_100]  148.34 77.52 180 top
J48  -  [ASP-134486-01]  11.84 80.31 90 top
J50  -  [694106301002]  165 55.41 180 top
J53  Header_2x7  [HEADER_2X7]  101.19 43.46 90 top
J54  -  [ASP-134486-01]  80.14 16.84 180 top
J57  Header_2x1  [HEADER_2X1]  114.68 138.35 90 top
J58  J-Header_2x1  [HEADER_2X1_100MIL]  45.8 107.46 0 top
J59  J-Header_2x1  [HEADER_2X1_100MIL]  94.67 107.16 270 top
J60  J-Header_2x1  [HEADER_2X1_100MIL]  56.69 83.9 0 top
J63  J-Header_2x1  [HEADER_2X1_100MIL]  65.02 117.24 270 top
J64  J-Header_2x1  [HEADER_2X1_100MIL]  69.06 107.54 270 top
J65  J-Header_2x1  [HEADER_2X1_100MIL]  71.68 117.24 270 top
J66  J-Header_2x1  [HEADER_2X1_100MIL]  80.63 117.24 270 top
J67  J-Header_2x1  [HEADER_2X1_100MIL]  89.9 117.24 270 top
J68  J-Header_2x1  [HEADER_2X1_100MIL]  107.7 119.27 270 top
J69  J-Header_2x1  [HEADER_2X1_100MIL]  116.59 119.27 270 top
J70  J-Header_2x1  [HEADER_2X1_100MIL]  95.76 117.24 270 top
J71  J-Header_2x1  [HEADER_2X1_100MIL]  114.6 112.37 180 top
J72  J-Header_2x1  [HEADER_2X1_100MIL]  83.9 103.05 270 top
J73  J-Header_2x1  [HEADER_2X1_100MIL]  109.09 94.41 270 top
J76  J-Header_2x1  [HEADER_2X1_100MIL]  100.57 117.24 90 top
J77  J-Header_2x1  [HEADER_2X1_100MIL]  102.7 98.68 0 top
J78  J-Header_2x1  [HEADER_2X1_100MIL]  110.11 48.31 0 top
J79  J-Header_2x1  [HEADER_2X1_100MIL]  114.64 107.98 180 top
J80  J-Header_2x1  [HEADER_2X1_100MIL]  114.68 103.86 180 top
J81  GND  [TUR_TH]  4.1 15.82 0 top
J83  Header_2x7  [HEADER_2X7]  128.65 8.43 0 top
J84  -  [1201M2S3AQE2]  146.59 39.92 90 top
JP1  JUMPER  [HEADER_1X2]  36.32 129.62 180 top
JP2  JUMPER  [HEADER_1X2]  36.32 132.92 180 top
JP3  JUMPER  [HEADER_1X2]  14.02 125.73 180 top
JP4  JUMPER  [HEADER_1X2]  36.32 126.41 180 top
JP5  JUMPER  [HEADER_1X2]  36.32 136.19 180 top
JP6  JUMPER  [HEADER_1X2]  12.45 139.78 90 top
JP12  JUMPER-DNI  [HEADER_1X2]  60.33 140.38 180 top
JP13  JUMPER-DNI  [HEADER_1X2]  51.56 140.38 0 top
JP15  JUMPER  [HEADER_1X2]  59.44 101.14 180 top
JP17  JUMPER  [HEADER_1X2]  44.32 140.38 0 top
JP26  Receptacle 20X2-DNI  [HDR254-2X20_SOCKET]  32.68 146.32 180 bottom
JP31  J-2 Pin Jumper  [0P1_2-PIN_TH]  123.95 120.11 180 top
JP32  J-2 Pin Jumper  [0P1_2-PIN_TH]  123.95 124.18 180 top
JP33  J-2 Pin Jumper  [0P1_2-PIN_TH]  123.95 107.92 180 top
JP34  J-2 Pin Jumper  [0P1_2-PIN_TH]  123.95 103.86 180 top
JP35  J-2 Pin Jumper  [0P1_2-PIN_TH]  123.95 116.05 180 top
JP36  J-2 Pin Jumper  [0P1_2-PIN_TH]  123.95 111.98 180 top
JP38  J-2 Pin Jumper  [0P1_2-PIN_TH]  51.86 96.06 90 top
JP40  J-2 Pin Jumper  [0P1_2-PIN_TH]  110.11 41.7 0 top
JP42  J-2 Pin Jumper  [0P1_2-PIN_TH]  110.11 45 0 top
JP47  J-2 Pin Jumper  [0P1_2-PIN_TH]  87.25 110.03 270 top
JP48  J-2 Pin Jumper  [0P1_2-PIN_TH]  82.68 110.03 270 top
JP49  J-2 Pin Jumper  [0P1_2-PIN_TH]  78.1 110.03 270 top
JP50  J-2 Pin Jumper  [0P1_2-PIN_TH]  73.53 110.03 270 top
JP51  J-2 Pin Jumper  [0P1_2-PIN_TH]  43.31 123.44 90 top
JP58  J-2 Pin Jumper  [0P1_2-PIN_TH]  88.63 127.68 0 top
JP59  J-2 Pin Jumper  [0P1_2-PIN_TH]  79.36 127.68 0 top
JP60  J-2 Pin Jumper  [0P1_2-PIN_TH]  71.93 127.68 0 top
JP61  J-2 Pin Jumper  [0P1_2-PIN_TH]  106.43 128.7 0 top
JP62  J-2 Pin Jumper  [0P1_2-PIN_TH]  115.32 128.7 0 top
JP64  3-PIN  [HDR254M-1X3]  56.09 36.76 180 top
JP65  3-PIN  [HDR254M-1X3]  51.86 106.03 270 top
JP69  J-2 Pin Jumper  [0P1_2-PIN_TH]  71.93 123.11 0 top
JP70  J-2 Pin Jumper  [0P1_2-PIN_TH]  71.93 132.25 0 top
JP71  J-2 Pin Jumper  [0P1_2-PIN_TH]  79.36 123.11 0 top
JP72  J-2 Pin Jumper  [0P1_2-PIN_TH]  79.36 132.25 0 top
JP73  J-2 Pin Jumper  [0P1_2-PIN_TH]  88.63 123.11 0 top
JP74  J-2 Pin Jumper  [0P1_2-PIN_TH]  88.63 132.25 0 top
JP75  J-2 Pin Jumper  [0P1_2-PIN_TH]  106.43 125.14 0 top
JP76  J-2 Pin Jumper  [0P1_2-PIN_TH]  106.43 132.25 0 top
JP77  J-2 Pin Jumper  [0P1_2-PIN_TH]  115.32 125.14 0 top
JP78  J-2 Pin Jumper  [0P1_2-PIN_TH]  115.32 132.25 0 top
JP83  3-PIN  [HDR254M-1X3]  126.11 86.41 90 top
JP84  3-PIN  [HDR254M-1X3]  126.11 77.14 90 top
JP85  3-PIN  [HDR254M-1X3]  119.13 49.83 0 top
JP86  3-PIN  [HDR254M-1X3]  119.13 54.15 0 top
JP88  3-PIN  [HDR254M-1X3]  48.26 96.82 90 top
JP89  3-PIN  [HDR254M-1X3]  44.7 96.82 90 top
L1  2.2uH SPM6530T-2R2M  [SPM6530T-2R2M]  32.8 51.94 90 top
L3  600ohm 500mA  [FB0603]  150.62 66.59 270 top
L4  3.3uH  [SRP4020TA-3R3M]  134.01 87.84 180 top
L5  3.3uH  [SRP4020TA-3R3M]  147.56 97.4 180 top
L6  600ohm 500mA  [FB0603]  151 64.18 180 top
L8  1.5uH  [SRP4020TA-1R5M]  147.99 139.82 180 top
L10  2.2uH SPM6530T-2R2M  [SPM6530T-2R2M]  28.22 16.79 180 top
L13  2.2uH SPM6530T-2R2M  [SPM6530T-2R2M]  21.84 34.72 270 top
L14  2.2uH SPM6530T-2R2M  [SPM6530T-2R2M]  36.96 34.72 270 top
L15  1.5uH  [SRP4020TA-1R5M]  147.99 110.61 180 top
L16  2.2uH  [SRP4020TA-2R2M]  133.37 101.02 180 top
L17  3.3uH  [SRP4020TA-3R3M]  133.34 129.66 180 top
L18  2.2uH  [SRP4020TA-2R2M]  133.27 115.24 180 top
L19  1uH  [SMD]  148.48 125.87 180 top
L20  2.2uH  [SRP4020TA-2R2M]  147.57 86.03 180 top
L21  4.7uH  [8MMX8MM]  118.83 39.57 180 top
L23  3.3uH  [SRP4020TA-3R3M]  136.93 49.57 180 top
L24  1.5uH  [L6R6X6R4-4R8]  130.43 23.67 0 top
L25  1.5uH  [L6R6X6R4-4R8]  138.3 23.67 180 top
NOREF  -  [unnamed]  3.68 8.68 0 top
NOREF#2  -  [unnamed]  3.68 146.32 0 top
NOREF#3  -  [#2]  3.68 8.68 0 top
NOREF#4  -  [unnamed]  161.32 146.32 0 top
NOREF#5  -  [unnamed]  160.03 139.36 0 top
NOREF#6  -  [unnamed]  161.32 8.68 0 top
NOREF#7  -  [#2]  165 5 0 top
NOREF#8  -  [#2]  0 150 0 top
NOREF#9  -  [#2]  3.68 8.68 0 top
NOREF#10  -  [unnamed]  2.54 140.61 0 top
NOREF#11  -  [unnamed]  61.68 146.32 180 top
NOREF#12  -  [#2]  165 5 0 top
NOREF#13  -  [unnamed]  8.51 12.11 0 top
NOREF#14  -  [#2]  0 150 0 top
NOREF#15  -  [unnamed]  8.51 12.11 180 bottom
NOREF#16  -  [unnamed]  160.88 138.99 180 bottom
NOREF#17  -  [unnamed]  3.4 140.24 180 bottom
P_DONE  VTTVREF  [TP_50]  153.29 85.01 0 top
P_INITN  VTTVREF  [TP_50]  156.24 90.38 0 top
P_JTAGENB  VTTVREF  [TP_50]  159.13 90.31 0 top
P_PROGN  VTTVREF  [TP_50]  153.29 87.68 0 top
PB1  TestPoint_SMT  [TPC32]  50.93 137.59 0 top
PB2  TestPoint_SMT  [TPC32]  58.42 137.59 0 top
PB3  TestPoint_SMT  [TPC32]  64.01 137.59 0 top
PLL0V82_EN  T POINT R  [TP]  155.61 63.44 0 top
PROGRAMN  TestPoint_SMT  [TPC32]  44.07 137.59 0 top
PS_EN  TestPoint_SMT  [TPC32]  124.08 43.41 0 top
PTM_SCL  VTTVREF  [TP_50]  159.13 84.88 0 top
PTM_SDA  VTTVREF  [TP_50]  156.24 87.67 0 top
Q1  MMBT2222ALT1G  [MMBT2222ALT-1]  58.68 109.1 0 bottom
Q2  BC817-40-TP  [SOT23-3]  77.6 143.05 90 bottom
Q3  BC817-40-TP  [SOT23-3]  82.17 142.92 270 bottom
Q4  BC817-40-TP  [SOT23-3]  69.98 143.43 90 bottom
Q7  BC817-40-TP  [SOT23-3]  158.28 124.13 90 bottom
Q8  BC817-40-TP  [SOT23-3]  158.28 120.58 90 bottom
Q9  BC817-40-TP  [SOT23-3]  158.28 106.39 90 bottom
Q10  BC817-40-TP  [SOT23-3]  158.28 117.03 90 bottom
Q11  BC817-40-TP  [SOT23-3]  158.28 102.84 90 bottom
Q12  BC817-40-TP  [SOT23-3]  158.28 109.94 90 bottom
Q13  BC817-40-TP  [SOT23-3]  158.28 127.68 90 bottom
Q14  BC817-40-TP  [SOT23-3]  158.28 113.49 90 bottom
Q15  BC817-40-TP  [SOT23-3]  158.28 134.77 90 bottom
Q16  BC817-40-TP  [SOT23-3]  42.29 9.57 0 bottom
Q17  BC817-40-TP  [SOT23-3]  38.23 9.57 0 bottom
Q18  BC817-40-TP  [SOT23-3]  34.16 9.57 0 bottom
Q19  BC817-40-TP  [SOT23-3]  30.1 9.57 0 bottom
Q20  BC817-40-TP  [SOT23-3]  26.04 9.57 0 bottom
Q21  BC817-40-TP  [SOT23-3]  21.97 9.57 0 bottom
Q22  BC817-40-TP  [SOT23-3]  17.91 9.57 0 bottom
Q23  BC817-40-TP  [SOT23-3]  13.84 9.57 0 bottom
Q24  BC817-40-TP  [SOT23-3]  158.28 131.23 90 bottom
Q26  MGSF1N02LT1G  [SOT23_MGSF1N02L]  156.99 79.17 0 top
Q27  BC817-40-TP  [SOT23-3]  135 146.22 90 bottom
Q28  BC817-40-TP  [SOT23-3]  129.03 146.22 90 bottom
Q29  BC817-40-TP  [SOT23-3]  110.87 146.35 270 bottom
Q30  BC817-40-TP  [SOT23-3]  121.28 146.35 270 bottom
Q31  BC817-40-TP  [SOT23-3]  116.08 146.35 270 bottom
Q32  BC817-40-TP  [SOT23-3]  95.76 146.22 270 bottom
Q33  BC817-40-TP  [SOT23-3]  105.66 146.35 270 bottom
Q34  BC817-40-TP  [SOT23-3]  100.71 146.35 270 bottom
R1  2.2K  [R0603]  7.37 138.89 0 top
R2  4.7k  [R0603]  19.21 121.75 0 top
R3  4.7k  [R0603]  26.83 121.75 0 top
R4  4.7k  [R0603]  30.9 121.75 180 top
R5  2.2K  [R0603]  14.13 121.75 180 top
R6  22  [R0402]  15.39 123.02 180 top
R7  0  [R0402]  27.09 123.02 0 top
R8  0  [R0402]  29.63 123.02 0 top
R9  0  [R0402]  19.47 123.02 0 top
R10  0-DNI  [R0402]  24.57 124.27 0 top
R11  2.2K  [R0603]  15.37 128.6 180 top
R12  10K  [R0603]  22.06 136.73 270 bottom
R13  10K  [R0603]  23.33 136.73 270 bottom
R14  10K  [R0603]  25.87 136.73 270 bottom
R15  12K  [R0603]  15.37 133.81 0 top
R16  10K  [R0603]  32 132.16 90 top
R17  10K  [R0603]  32 129.11 270 top
R19  2.2K  [R0603]  24.6 136.73 90 bottom
R20  0  [R0402]  71.02 99.03 270 bottom
R21  4.7k  [R0603]  51.56 133.78 180 bottom
R22  10k  [R0603]  62.94 108.2 180 bottom
R23  100  [R0402]  51.56 135.17 0 bottom
R24  1K  [R0603]  62.89 109.77 0 bottom
R25  1K  [R0603]  58.6 111.94 180 bottom
R26  10k  [R0603]  55.92 106.53 90 bottom
R27  4.7k  [R0603]  44.83 133.78 180 bottom
R28  10k  [R0603]  55.9 109.53 270 bottom
R29  100  [R0402]  44.7 135.43 0 bottom
R30  4.7k  [R0603]  60.21 49.84 90 bottom
R31  4.7k  [R0603]  58.94 49.84 90 bottom
R32  4.7k  [R0603]  57.67 49.84 90 bottom
R33  4.7k  [R0603]  56.4 49.84 90 bottom
R34  4.7k  [R0603]  55.13 49.84 90 bottom
R35  4.7k  [R0603]  53.86 49.84 90 bottom
R36  4.7k  [R0603]  52.59 49.84 90 bottom
R37  4.7k  [R0603]  51.32 49.84 90 bottom
R38  10K  [R0402]  47.5 124.89 270 bottom
R39  10K-DNI  [R0402]  47.75 120.57 0 top
R40  10K-DNI  [R0402]  59.56 121.59 180 top
R41  10K-DNI  [R0402]  59.56 122.98 180 top
R42  4.7k  [R0603]  129.92 56.31 0 bottom
R43  0  [R0402]  47.75 122.98 0 top
R44  0  [R0402]  59.61 124.09 180 top
R45  0  [R0402]  47.75 121.71 180 top
R46  0  [R0402]  59.56 120.06 180 top
R47  4.7k  [R0603]  59.05 133.78 180 bottom
R48  4.7k  [R0603]  64.26 133.78 180 bottom
R50  100  [R0402]  59.18 135.17 0 bottom
R51  100  [R0402]  64.39 135.05 0 bottom
R52  2.2  [R0603]  142.88 73.45 180 bottom
R54  4.99k  [R0402]  135.25 63.29 90 top
R55  22  [R0402]  61.42 85.83 0 bottom
R56  330R  [R0603]  138.29 144.34 90 bottom
R57  330R  [R0603]  140.71 144.34 90 bottom
R58  330R  [R0603]  143.25 144.34 90 bottom
R59  330R  [R0603]  145.79 144.34 90 bottom
R60  330R  [R0603]  148.33 144.34 90 bottom
R61  330R  [R0603]  150.74 144.34 90 bottom
R62  330R  [R0603]  153.28 144.34 90 bottom
R63  330R  [R0603]  155.82 144.34 90 bottom
R76  4.7k  [R0603]  146.6 75.44 180 bottom
R77  2.2K  [R0603]  131.23 75.57 0 bottom
R78  4.7k  [R0603]  142.53 75.44 0 bottom
R79  4.7k  [R0603]  136.31 75.44 180 bottom
R80  100  [R0402]  133.35 56.31 0 bottom
R81  10K  [R0603]  152.02 74.72 270 bottom
R82  0.01  [R0603]  134.49 135.3 180 top
R83  10k  [R0603]  20.09 106.6 0 bottom
R84  10k  [R0603]  10.44 106.6 180 bottom
R85  4.7k  [R0603]  40.88 60.17 270 bottom
R86  4.7k  [R0603]  43.42 60.17 270 bottom
R87  4.7k  [R0603]  48.5 60.17 270 bottom
R90  4.7k  [R0603]  20.09 68.12 0 bottom
R91  4.7k  [R0603]  20.09 66.72 0 bottom
R92  2.2K  [R0603]  35.8 60.17 270 bottom
R95  1k  [R0603]  38.16 53.29 180 top
R96  1K  [R0402]  46.39 47.14 90 top
R100  301  [R0402]  45.09 47.14 270 top
R103  0-DNI  [R0603]  60.88 89.59 180 bottom
R104  0-DNI  [R0603]  60.88 88.16 180 bottom
R105  0-DNI  [R0402]  61.47 80.69 0 bottom
R106  22-DNI  [R0402]  61.42 83.09 0 bottom
R107  0-DNI  [R0402]  61.42 84.9 0 bottom
R108  0-DNI  [R0402]  61.47 81.83 0 bottom
R109  10K  [R0603]  58.42 98.09 0 top
R110  22  [R0402]  60.33 91.36 180 top
R126  2.2K  [R0603]  155.83 82.22 270 bottom
R127  2.2K  [R0603]  157.23 82.22 270 bottom
R137  0.01  [R0603]  74.55 117.27 270 top
R139  0.01  [R0603]  45.76 103.42 0 top
R140  0.01  [R0603]  56.21 86.22 0 top
R142  0.01  [R0603]  77.6 117.27 270 top
R143  0.01  [R0603]  91.81 105.79 90 top
R147  0.01  [R0603]  86.87 117.14 270 top
R154  0.1  [0603]  98.35 117.26 90 bottom
R169  330R  [R0603]  161.63 124.12 180 bottom
R179  10k  [R0402]  40.33 112.48 0 bottom
R180  10k  [R0402]  35.47 107.53 0 bottom
R185  4.7k  [R0603]  95.25 126.92 90 bottom
R189  0  [R0603]  98.3 125.52 270 bottom
R192  10K-DNI  [R0402]  97.79 127.68 0 bottom
R215  0-DNI  [R0603]  20.09 105.2 0 bottom
R216  0-DNI  [R0603]  18.92 55.83 0 bottom
R217  10k  [R0603]  7.52 106.6 0 bottom
R229  10K  [R0603]  155.61 123.95 90 bottom
R231  2.61K  [0603]  152.91 132.81 90 top
R232  10K  [R0603]  151.51 132.81 270 top
R233  18.2 k  [RES0402]  152.81 134.97 180 top
R234  12.7 k  [RES0402]  152.81 136.24 0 top
R245  0-DNI  [R0402]  108.2 37 90 top
R249  4.7k-DNI  [R0603]  13.46 63.17 90 bottom
R250  4.7k-DNI  [R0603]  16.66 64.18 90 bottom
R251  1k  [R0603]  12.06 62.38 270 bottom
R252  1k  [R0603]  18.06 62.25 90 bottom
R267  1R  [0603]  101.28 94.08 0 top
R287  19.1K  [R0603]  162.43 73.96 180 bottom
R288  19.1K-DNI  [R0603]  162.94 76.25 270 bottom
R289  1.4K  [R0603]  163.19 68.88 270 top
R290  240  [R0402]  93.6 71.17 270 bottom
R291  240  [R0402]  106.93 78.91 90 bottom
R292  4.7k  [R0603]  122.81 88.44 90 bottom
R293  4.7k  [R0603]  122.68 74.09 180 bottom
R294  240  [R0402]  89.92 80.18 270 bottom
R298  0.01  [R0603]  111.25 135.05 180 top
R305  1K  [R0402]  30.61 29.76 270 top
R306  301  [R0402]  32.13 29.76 90 top
R307  1k  [R0603]  27.6 22.1 270 top
R308  0-DNI  [R0603]  53.85 25.09 90 bottom
R309  0-DNI  [R0603]  104.78 23.14 90 bottom
R310  10k  [R0603]  53.85 12.52 90 bottom
R314  4.7k  [R0603]  104.65 43.48 90 bottom
R315  4.7k  [R0603]  104.65 46.78 90 bottom
R316  4.7k  [R0603]  104.65 50.34 270 bottom
R317  2.2K  [R0603]  104.83 37.64 270 bottom
R321  4.7k  [R0603]  92.46 23.67 90 bottom
R322  4.7k  [R0603]  93.98 23.67 90 bottom
R323  4.7k-DNI  [R0603]  96.34 21.51 180 bottom
R324  4.7k-DNI  [R0603]  97.99 18.74 180 bottom
R325  1k  [R0603]  97.28 23.16 0 bottom
R326  1k  [R0603]  99.57 16.81 180 bottom
R327  10k  [R0603]  55.24 25.09 90 bottom
R328  10k  [R0603]  53.85 15.44 270 bottom
R331  53.6R  [RES0402]  76.06 137.02 270 bottom
R332  53.6R  [RES0402]  73.03 144.32 180 bottom
R333  53.6R  [RES0402]  86.74 146.35 0 bottom
R334  53.6R  [RES0402]  78.62 137.03 270 bottom
R335  53.6R  [RES0402]  73.55 136.98 270 bottom
R336  53.6R  [RES0402]  71.01 137.01 270 bottom
R337  53.6R  [RES0402]  75.08 144.32 180 bottom
R338  53.6R  [RES0402]  81.14 136.96 270 bottom
R339  330R  [R0603]  74.42 142.29 0 bottom
R340  4.7K  [R0603]  74.42 140.64 180 bottom
R341  330R  [R0603]  84.96 143.56 90 bottom
R342  4.7K  [R0603]  86.61 143.56 270 bottom
R343  330R  [R0603]  66.8 142.79 0 bottom
R344  4.7K  [R0603]  66.8 141.14 180 bottom
R345  22  [R0402]  78.61 80.06 180 bottom
R353  0.01  [R0603]  114.68 114.47 180 bottom
R370  0.01  [R0603]  113.54 119.3 270 top
R374  0.01  [R0603]  92.84 117.01 270 top
R378  0.01  [R0603]  104.78 119.3 270 top
R387  0.01  [R0603]  81.51 102.91 270 top
R391  0.01  [R0603]  68.07 117.14 270 top
R395  0.01  [R0603]  66.23 107.3 270 top
R398  10k  [R0402]  69.09 98.98 90 bottom
R399  20k  [R0603]  30.86 36.5 0 top
R401  10k  [R0603]  30.1 38.78 270 top
R402  20k  [R0603]  46.74 38.78 90 top
R406  10k  [R0603]  45.34 38.78 270 top
R408  0-DNI  [R0402]  61.42 86.74 0 bottom
R411  330R  [R0603]  162.08 90.83 180 bottom
R412  18.2 k  [RES0402]  138.82 83 180 top
R413  12.7 k  [RES0402]  138.82 84.27 0 top
R414  31.6K  [R0603]  138.92 80.83 90 top
R415  10K  [0603]  137.52 80.83 270 top
R416  10K  [R0603]  155.61 120.4 90 bottom
R417  330R  [R0603]  161.63 120.58 180 bottom
R418  18.2 k  [RES0402]  152.81 105.76 180 top
R419  12.7 k  [RES0402]  152.81 107.03 0 top
R420  3.83K  [0603]  152.91 103.6 90 top
R421  10K  [R0603]  151.51 103.6 270 top
R424  10K  [R0603]  151.07 90.38 270 top
R425  12.7 K  [RES0402]  152.47 90.38 90 top
R426  10K  [R0603]  155.61 106.21 90 bottom
R427  330R  [R0603]  161.63 106.39 180 bottom
R428  18.2 k  [RES0402]  138.15 96.08 180 top
R429  12.7 k  [RES0402]  138.15 97.35 0 top
R430  10K  [R0603]  136.86 93.92 270 top
R431  5.11K  [0603]  138.25 93.92 90 top
R432  10K  [R0603]  155.61 116.86 90 bottom
R433  330R  [R0603]  161.63 117.03 180 bottom
R434  18.2 k  [RES0402]  138.15 124.81 180 top
R435  12.7 k  [RES0402]  138.15 126.08 0 top
R436  10K  [R0603]  136.86 122.65 270 top
R437  21.5K  [0603]  138.25 122.65 90 top
R438  10K  [R0603]  155.61 102.67 90 bottom
R439  330R  [R0603]  161.63 102.84 180 bottom
R440  12.7 k  [RES0402]  138.15 111.6 0 top
R441  18.2 k  [RES0402]  138.15 110.33 180 top
R442  10K  [R0603]  136.86 108.17 270 top
R443  10K  [R0603]  155.61 109.76 90 bottom
R444  330R  [R0603]  161.63 109.93 180 bottom
R445  8.87K  [0603]  138.25 108.17 90 top
R446  10K  [R0603]  155.61 127.5 90 bottom
R447  330R  [R0603]  161.63 127.67 180 bottom
R448  18.2 k  [RES0402]  152.81 120.49 180 top
R449  12.7 k  [RES0402]  152.81 121.76 0 top
R450  1.33K  [0603]  152.91 118.33 90 top
R451  10K  [R0603]  151.51 118.33 270 top
R452  10K  [R0603]  155.61 113.31 90 bottom
R453  330R  [R0603]  161.63 113.48 180 bottom
R454  18.2 k  [RES0402]  152.47 81.2 180 top
R455  12.7 k  [RES0402]  152.47 82.47 0 top
R456  6.98K  [0603]  152.57 79.04 90 top
R457  10K  [R0603]  151.18 79.04 270 top
R463  4.3K  [0603]  124.36 44.83 180 top
R464  176K  [0603]  128.06 45.66 270 top
R465  24K  [0603]  126.58 45.66 90 top
R466  100K  [R0603]  127.44 37.76 90 top
R467  100K  [R0603]  126.11 37.77 90 top
R474  10K  [R0603]  155.61 134.6 90 bottom
R475  330R  [R0603]  161.63 134.77 180 bottom
R490  49.9  [R0402]  99.69 74.6 90 bottom
R491  49.9  [R0402]  99.69 72.56 90 bottom
R492  2K-DNI  [R0402]  99.19 78.66 180 bottom
R493  2K-DNI  [R0402]  99.19 77.64 0 bottom
R510  1K  [R0402]  161.3 86.64 0 bottom
R519  3.6K  [R0402]  161.3 82.44 0 bottom
R520  10K  [R0603]  42.16 12.24 0 bottom
R521  330R  [R0603]  42.29 6.9 180 bottom
R522  10K  [R0603]  38.23 12.24 0 bottom
R523  330R  [R0603]  38.23 6.9 180 bottom
R524  330R  [R0603]  34.16 6.9 180 bottom
R525  10K  [R0603]  34.16 12.24 0 bottom
R526  330R  [R0603]  30.1 6.9 180 bottom
R527  10K  [R0603]  29.97 12.24 0 bottom
R528  330R  [R0603]  26.04 6.9 180 bottom
R529  330R  [R0603]  21.97 6.9 180 bottom
R530  10K  [R0603]  25.91 12.24 0 bottom
R531  10K  [R0603]  21.84 12.24 0 bottom
R532  330R  [R0603]  17.91 6.9 180 bottom
R533  330R  [R0603]  13.84 6.9 180 bottom
R534  10K  [R0603]  17.78 12.24 0 bottom
R535  10K  [R0603]  13.72 12.24 0 bottom
R536  0  [R0402]  60.33 137.97 0 bottom
R537  0  [R0402]  100.84 87.8 90 top
R538  0  [R0402]  101.85 87.8 90 top
R539  1R  [0603]  109.51 51.44 0 top
R540  1R  [0603]  114.55 110.16 180 bottom
R541  1R  [0603]  114.55 105.84 180 bottom
R542  4.7k  [R0603]  78.7 59.99 270 bottom
R543  4.7k  [R0603]  80.15 59.99 270 bottom
R544  2K  [R0603]  100.42 106.46 270 top
R545  80.6K  [0603]  99.02 106.46 90 top
R546  330R  [R0603]  161.63 131.22 180 bottom
R547  10K  [R0603]  155.61 131.05 90 bottom
R548  0  [R0402]  99.19 76.63 0 bottom
R549  22  [R0402]  155.7 79.68 270 bottom
R550  22  [R0402]  157.1 78.15 270 bottom
R551  22  [R0402]  154.3 76.63 270 bottom
R552  22  [R0402]  155.7 76.63 270 bottom
R554  1k  [R0603]  163.19 71.93 270 top
R556  10K  [R0603]  102.04 104.14 180 bottom
R561  5.9K-DNI  [0603]  144.53 61.77 0 top
R562  5.9K  [0603]  160.02 67.48 90 bottom
R563  3.4K-DNI  [0603]  163.19 70.28 90 bottom
R564  3.4K  [0603]  162.43 72.56 180 bottom
R565  5.62K  [0603]  142.28 49.74 270 top
R566  31.6K  [R0603]  142.88 43.86 180 top
R567  330R  [R0603]  161.67 78.91 180 bottom
R568  3.01K  [0402]  142.92 45.27 0 top
R569  10K  [R0603]  142.88 42.46 0 top
R572  10K  [R0402]  152.53 93.65 180 top
R575  0  [R0402]  100.33 67.1 0 top
R576  0  [R0402]  100.33 66.09 0 top
R577  0  [R0402]  141.35 95.3 270 top
R578  33R  [0603]  159.51 80.95 270 top
R579  330R  [R0603]  157.48 76.88 180 top
R582  100-DNI  [R0201]  114.55 67.52 270 bottom
R583  0  [R0402]  99.83 63.93 270 top
R584  0  [R0402]  100.85 63.93 270 top
R585  1k  [R0402]  156.58 99.02 90 top
R588  10K-DNI  [R0603]  129.46 45.65 90 top
R589  3.4K-DNI  [0603]  130.68 45.65 270 top
R596  4.7k  [R0603]  116.08 86.03 180 bottom
R597  1k  [R0402]  123.32 79.17 0 bottom
R598  1k  [R0402]  123.32 83.36 0 bottom
R599  10  [R0402]  144.78 14.27 270 top
R600  10  [R0402]  145.8 14.27 270 top
R601  0  [R0402]  149.1 11.48 0 top
R602  0  [R0402]  149.1 10.46 0 top
R603  4.7k  [R0603]  122.43 13.76 270 bottom
R604  4.7k  [R0603]  125.22 13.76 270 bottom
R605  4.7k  [R0603]  130.81 13.76 270 top
R606  4.7k  [R0603]  122.43 13.76 270 top
R607  4.7k  [R0603]  121.03 13.76 270 top
R608  4.7k  [R0603]  133.6 13.76 270 top
R609  100K  [R0603]  121.41 18.46 90 top
R610  100K  [R0603]  147.27 28.88 270 top
R611  15K  [R0603]  151 28.24 180 top
R612  15K  [R0603]  117.73 20.49 0 top
R613  10K  [R0603]  148.54 28.88 270 top
R614  10K  [R0603]  121.41 18.46 90 bottom
R615  0  [R0603]  117.73 17.7 0 top
R616  0-DNI  [R0603]  120.01 18.46 270 top
R617  12.1K  [R0603]  151 29.64 180 top
R618  100K  [R0603]  117.73 19.1 0 top
R619  100K  [R0603]  117.73 23.29 180 top
R620  5.23K  [R0603]  117.73 21.89 180 top
R621  5.23K  [R0603]  151 26.84 0 top
R622  100K  [R0603]  151 24.05 0 top
R623  4.7K-DNI  [R0603]  125.22 13.76 270 top
R624  10k  [R0603]  27.3 38.15 180 bottom
R625  4.7k  [R0603]  27.3 36.88 180 bottom
R628  10k  [R0603]  42.42 38.15 180 bottom
R629  4.7k  [R0603]  42.42 36.88 180 bottom
R633  240  [R0402]  106.93 65.2 90 bottom
R636  100-DNI  [R0201]  114.55 81.24 270 bottom
R638  0  [R0603]  160.02 29.38 90 top
R639  10K-DNI  [R0603]  161.42 29.38 90 top
R640  31.6K  [R0603]  154.43 29.38 270 top
R641  10K  [R0603]  156.72 31.29 0 top
R642  0  [R0603]  151 21.26 0 top
R643  0  [R0603]  117.73 27.48 180 top
R644  1k  [R0402]  121.16 56.31 0 bottom
R645  1k  [R0402]  117.09 51.99 180 bottom
R646  4.7k  [R0603]  124.46 50.59 90 bottom
R647  4.7k  [R0603]  116.84 57.07 0 bottom
R648  10  [R0402]  148.08 12.49 270 bottom
R649  0-DNI  [R0603]  151 18.46 0 top
R650  0-DNI  [R0603]  117.73 30.27 180 top
R651  0  [R0603]  126.62 13.76 90 top
R652  240  [R0402]  61.34 72.69 90 bottom
R653  240  [R0402]  61.34 68.88 90 bottom
R654  240  [R0402]  61.34 66.72 270 bottom
R655  240  [R0402]  83.69 61.77 0 bottom
R656  240  [R0402]  87.25 60.63 180 bottom
R657  0  [R0402]  53.47 86.41 180 bottom
R658  0.002ohm  [R3637]  116.97 94.79 270 top
R659  4.7K-DNI  [R0603]  128.02 13.76 270 bottom
R660  4.7K-DNI  [R0603]  130.81 13.76 270 bottom
R661  4.7K-DNI  [R0603]  133.6 13.76 270 bottom
R662  4.7K-DNI  [R0603]  135 13.76 270 bottom
R663  0-DNI  [R0603]  121.03 13.76 90 bottom
R664  0-DNI  [R0603]  123.82 13.76 90 bottom
R665  0-DNI  [R0603]  126.62 13.76 90 bottom
R666  0-DNI  [R0603]  129.41 13.76 90 bottom
R667  0-DNI  [R0603]  132.21 13.76 90 bottom
R668  0-DNI  [R0603]  136.4 13.76 90 bottom
R669  0-DNI  [R0603]  136.4 13.76 270 top
R670  0-DNI  [R0603]  129.41 13.76 270 top
R671  0-DNI  [R0603]  119.63 13.76 270 top
R672  0-DNI  [R0603]  123.82 13.76 270 top
R673  0-DNI  [R0603]  132.21 13.76 270 top
R674  0-DNI  [R0603]  135 13.76 270 top
R675  4.7K-DNI  [R0603]  128.02 13.76 270 top
R676  4.7K-DNI  [R0603]  137.79 13.76 270 top
R680  1k-DNI  [R0603]  162.43 77.01 180 top
R681  1k-DNI  [R0603]  163.19 74.85 90 top
R682  0-DNI  [R0603]  140.33 80.82 90 top
R683  10K  [R0603]  132.08 145.97 90 bottom
R684  10K  [R0603]  126.37 145.97 90 bottom
R685  240  [R0402]  90.04 72.44 90 bottom
R686  1k  [R0402]  59.56 77.9 180 top
R687  31.6K  [R0603]  113.41 146.35 270 bottom
R688  31.6K  [R0603]  123.82 146.22 270 bottom
R689  31.6K  [R0603]  118.62 146.35 270 bottom
R690  31.6K  [R0603]  98.17 146.22 270 bottom
R691  31.6K  [R0603]  108.2 146.35 270 bottom
R692  31.6K  [R0603]  103.25 146.35 270 bottom
R693  10K  [R0402]  139.83 73.45 270 top
R694  10K  [R0402]  137.03 73.96 0 top
R695  0  [R0402]  137.03 72.94 180 top
R696  60.4K  [R0603]  137.16 63.29 270 top
